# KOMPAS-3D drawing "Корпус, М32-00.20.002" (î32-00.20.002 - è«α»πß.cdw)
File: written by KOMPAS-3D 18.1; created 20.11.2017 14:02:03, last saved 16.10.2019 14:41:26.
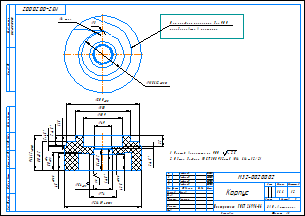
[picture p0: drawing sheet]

Sheet 1: A3, landscape

Document properties: Полное имя файла: D:\Magna\Магна Ins\Магна ins 32\Для Караби\М32-00.20.002 - Корпус.cdw; Масса: 1.66329

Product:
- Part/product: Корпус  | designation М32-00.20.002  | pos. 0
    Материал: Полипропилен  ГОСТ 26996-86 (density 900 kg/m3)
    Масса: 1.66329
    Раздел спецификации: Детали
    Форматы листов документа: A3
    source file: М32-00.20.002 - Корпус.cdw

Title block, sheet 1: Наименование: Корпус; designation: М32-00.20.002; Материал: Полипропилен  ГОСТ 26996-86; Масса: 1,66; scale: 1:2; Количество листов документа: 1; organisation: ЗАО «Астерион»; Форматы листов документа: A3; stored path: D:\Отработать\Магна 40\Чертежи\М40-00.20.002 - Корпус.cdw; Разработал: Милов; Т. контр.: Лучихин

Views: Вид 1, Спереди, Проекционный вид 2, Местный разрез 1
Referenced files in D:\Отработать\Магна 40\3Д\: М40-00.20.002 - Корпус.m3d
Referenced files in Z:\Магна\Магна Ins\Магна ins 32\: М32-00.20.002 - Корпус.m3d
Referenced files in D:\Magna\Магна Ins\Магна ins 32\: М32-00.20.002 - Корпус.m3d
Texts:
  При загрузки программы для ЧПУ
  преобразовать в полилинию
  max
  Лифлянд
Dimensions and other numbers on the sheet: 118; 4; 3; 109; 1; 96; 45; 56±0,2; 50; 43,5; 150; 74; 32; 80±0,2; 2; 214; 200; 11,5; 49; 54; 2,5; 1:2; 1,66; 01.07.2019; 12.07.2019; 22.08.2019; 16.10.2019

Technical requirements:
  Улитку выполнить на ЧПУ,  Ra 2,5 .
  Общие допуски ГОСТ 30893.2-mK (H14, h14,  t2/2).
